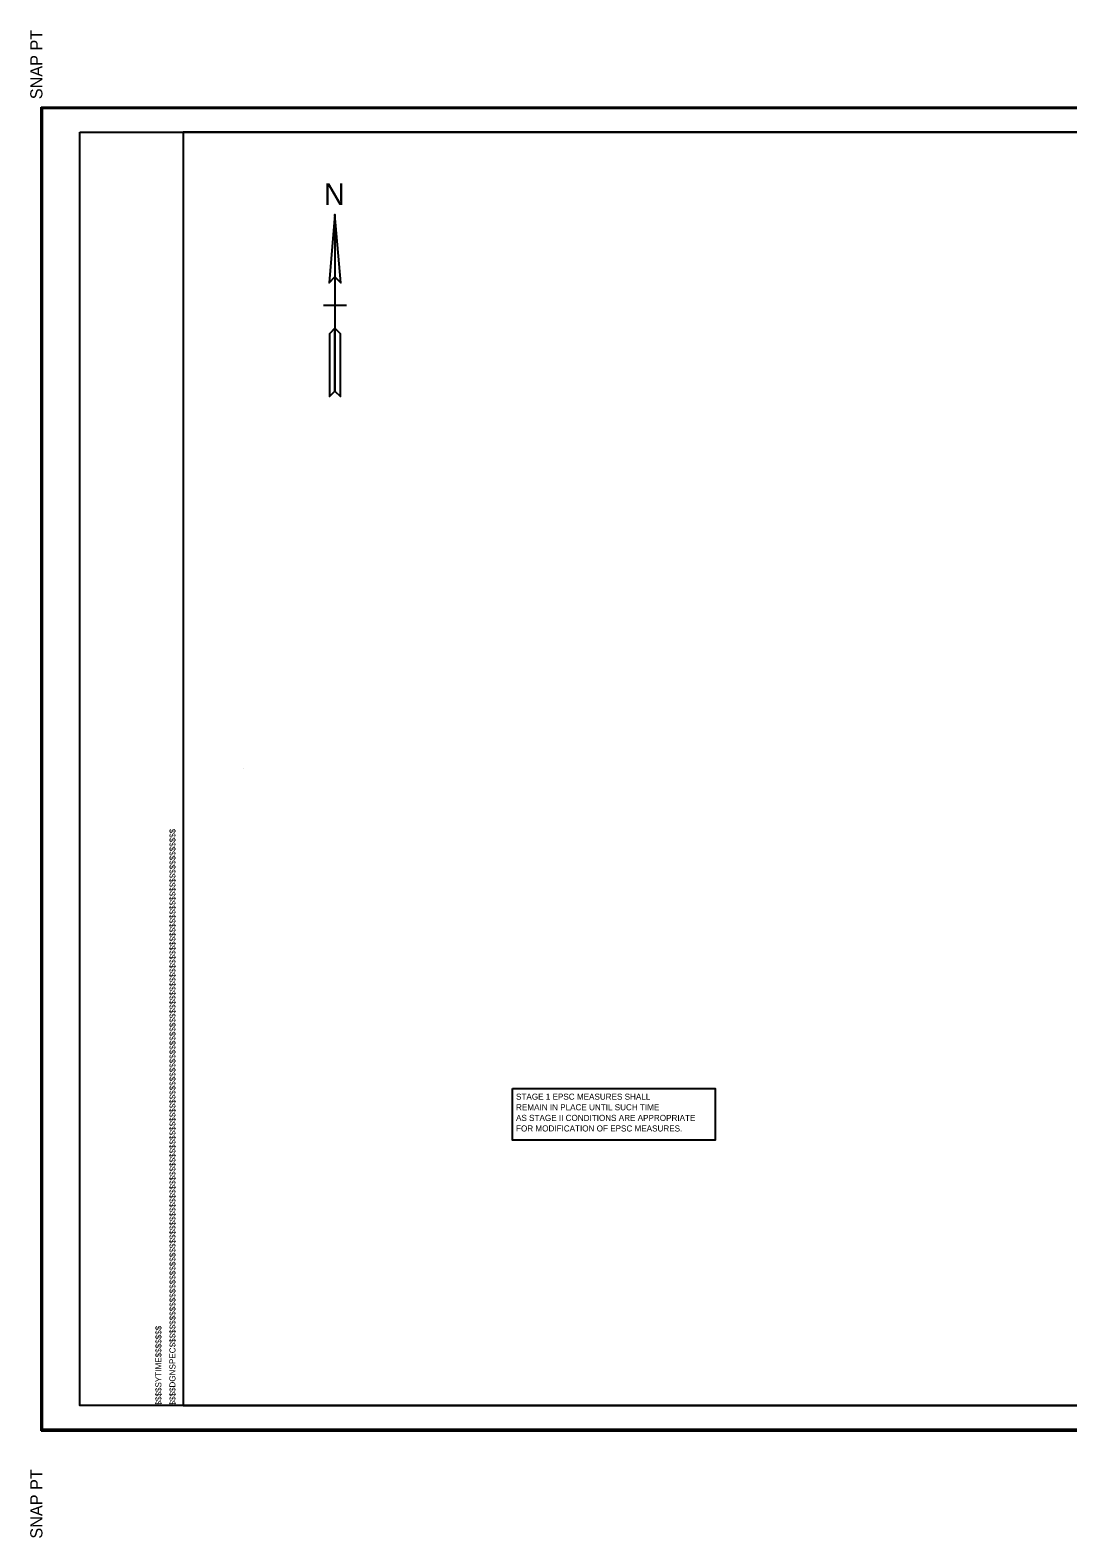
# Model space of a CAD drawing. Extents: x -200 to 1681714, y -325 to 518733.
# Drawn here: x 1680003 to 1680858, y 517490 to 518733 of the extents above; entities that cross this region are included whole.
import ezdxf

# ---------------------------------------------------------------- set-up
doc = ezdxf.new("R2010")
doc.units = 0
for name, color, linetype in [('DESIGN - CENTERLINE - Proposed Text', 7, 'Continuous'), ('DESIGN - EROSION CONTROL - Devices Text and Legends', 7, 'Continuous'), ('DESIGN - SCRATCH - User 1', 7, 'Continuous'), ('DESIGN - SHEET - Corner Text', 7, 'Continuous'), ('DESIGN - SHEET - Linework', 7, 'Continuous'), ('DESIGN - SHEET - Plot Shape', 7, 'Continuous')]:
    doc.layers.add(name, color=color, linetype=linetype)

msp = doc.modelspace()

# ---------------------------------------------------------------- linework, layer by layer
at = {"layer": 'DESIGN - CENTERLINE - Proposed Text'}
for p, q in [((1680254.1, 518506), (1680244.7, 518506)), ((1680263.6, 518506), (1680254.1, 518506))]:
    msp.add_line(p, q, dxfattribs=at)
msp.add_lwpolyline([(1680254.1, 518581), (1680249.2, 518524.7), (1680254.1, 518529.6), (1680259, 518524.7), (1680254.1, 518581), (1680254.1, 518435.5), (1680258.7, 518431), (1680258.7, 518482.7), (1680254.1, 518487.3), (1680249.6, 518482.7), (1680249.6, 518431), (1680254.1, 518435.5)], dxfattribs=at)
for points in [[(1680254.1, 518529.6), (1680259, 518524.7), (1680254.1, 518581)], [(1680249.6, 518431), (1680254.1, 518435.5), (1680254.1, 518487.3), (1680249.6, 518482.7)]]:
    msp.add_lwpolyline(points, close=True, dxfattribs=at)
at = {"layer": 'DESIGN - EROSION CONTROL - Devices Text and Legends'}
msp.add_lwpolyline([(1680400.5, 517860.3), (1680567.7, 517860.3), (1680567.7, 517817.9), (1680400.5, 517817.9)], close=True, dxfattribs=at)
at = {"layer": 'DESIGN - SCRATCH - User 1'}
msp.add_line((1680178.9, 518124), (1680178.9, 518124), dxfattribs=at)
at = {"layer": 'DESIGN - SHEET - Linework'}
for p, q in [((1680011.9, 517578.3), (1680011.9, 518669.7)), ((1680011.9, 518669.7), (1681713.9, 518669.7)), ((1680011.9, 517578.3), (1681713.9, 517578.3))]:
    msp.add_line(p, q, dxfattribs=at)
msp.add_lwpolyline([(1680128.9, 518649), (1680128.9, 517599), (1681703.1, 517599), (1681703.1, 518649), (1680128.9, 518649)], dxfattribs=at)
at = {"layer": 'DESIGN - SHEET - Plot Shape'}
for points in [[(1680012.9, 518668.7), (1681712.9, 518668.7), (1681712.9, 517579.3), (1680012.9, 517579.3)], [(1680043.8, 518649), (1681703.1, 518649), (1681703.1, 517599), (1680043.8, 517599)]]:
    msp.add_lwpolyline(points, close=True, dxfattribs=at)

# ---------------------------------------------------------------- texts
at = {"layer": 'DESIGN - CENTERLINE - Proposed Text'}
msp.add_text('N', height=17.7, dxfattribs=at).set_placement((1680245.1, 518589))
at = {"layer": 'DESIGN - EROSION CONTROL - Devices Text and Legends'}
for s, p in [('STAGE 1 EPSC MEASURES SHALL ', (1680403.4, 517851.2)), ('REMAIN IN PLACE UNTIL SUCH TIME', (1680403.4, 517842.5)), ('AS STAGE II CONDITIONS ARE APPROPRIATE', (1680403.4, 517833.7)), ('FOR MODIFICATION OF EPSC MEASURES.', (1680403.4, 517825))]:
    msp.add_text(s, height=5, dxfattribs=at).set_placement(p)
at = {"layer": 'DESIGN - SHEET - Corner Text'}
for s, height, p in [('  SNAP PT', 10, (1680012.9, 518668.7)), ('$$$$DGNSPEC$$$$$$$$$$$$$$$$$$$$$$$$$$$$$$$$$$$$$$$$$$$$$$$$$$$$$$$$$$$$$$$$$$$$$$$$$$$$$$$$$$$$$$$$$$$$$$$$$$$$$$$$$$$$$$$$$$$', 5.0001, (1680122.6, 517599)), ('$$$$SYTIME$$$$$$$', 5, (1680111, 517599)), ('SNAP PT  ', 10, (1680012.9, 517489.3))]:
    msp.add_text(s, height=height, rotation=90, dxfattribs=at).set_placement(p)

doc.saveas('drawing.dxf')
